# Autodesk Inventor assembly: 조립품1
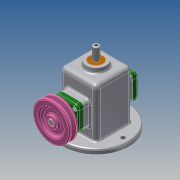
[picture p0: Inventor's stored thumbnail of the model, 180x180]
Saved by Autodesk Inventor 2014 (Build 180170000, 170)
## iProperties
Created: 2021-08
Part Number: 조립품1
Document SubType Name: Assembly
Designer: kb542-02
Author: kb542-02
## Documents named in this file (16)
- C:\Users\kb542-02\Desktop\710806V1011\조립품1.iam
- C:\Users\kb542-02\Desktop\710806V1011\본체.ipt
- C:\Users\kb542-02\Desktop\710806V1011\V벨트풀리.ipt
- C:\Users\kb542-02\Desktop\710806V1011\고정핀 1.2x8.ipt
- C:\Users\kb542-02\Desktop\710806V1011\뒤커버.ipt
- C:\Users\kb542-02\Desktop\710806V1011\링크.ipt
- C:\Users\kb542-02\Desktop\710806V1011\멈춤나사 M3x8.ipt
- C:\Users\kb542-02\Desktop\710806V1011\베어링 12x32x10.ipt
- C:\Users\kb542-02\Desktop\710806V1011\볼트 M4.ipt
- C:\Users\kb542-02\Desktop\710806V1011\부시.ipt
- C:\Users\kb542-02\Desktop\710806V1011\슬라이드.ipt
- C:\Users\kb542-02\Desktop\710806V1011\앞커버.ipt
- C:\Users\kb542-02\Desktop\710806V1011\오일 실 12 25 7.ipt
- C:\Users\kb542-02\Desktop\710806V1011\키 4x4x10.ipt
- C:\Users\kb542-02\Desktop\710806V1011\편심축.ipt
- C:\Users\kb542-02\Desktop\710806V1011\핀 5x18.ipt
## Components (3 placed, 3 different names)
1. V벨트풀리:1 — 플러쉬:1
2. 고정핀 1.2x8:1
3. 핀 5x18:1
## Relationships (1: Flush 1)
- 플러쉬:1 [Flush]: V벨트풀리:1
